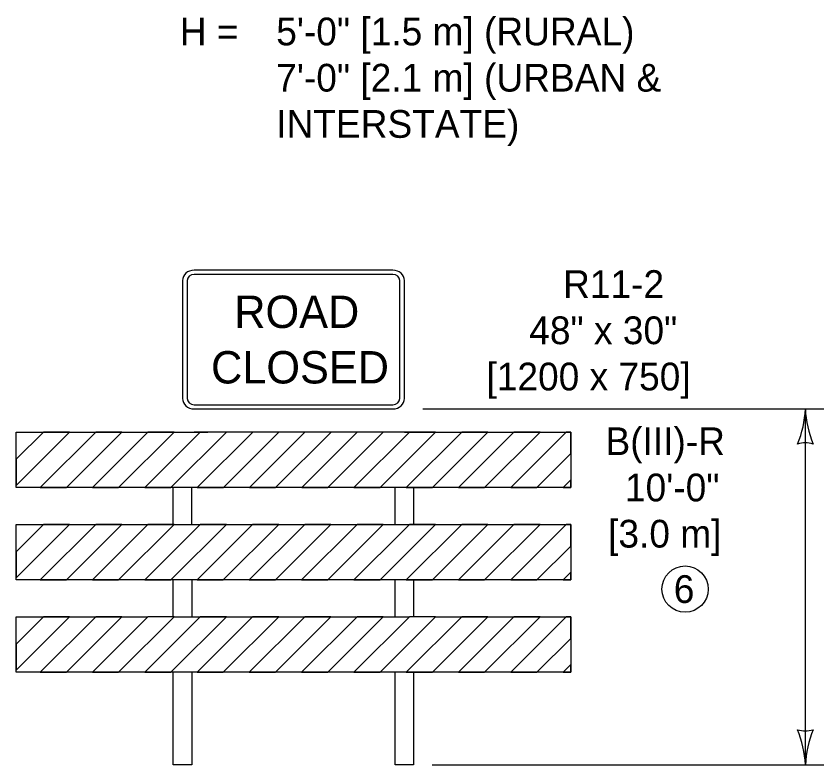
# Model space of a CAD drawing. Extents: x 49991.4 to 50021, y 49987.6 to 50011.4.
# Drawn here: x 50009.205 to 50010.952, y 49991.725 to 49993.345 of the extents above; entities that cross this region are included whole.
import ezdxf

# ---------------------------------------------------------------- set-up
doc = ezdxf.new("R2010")
doc.units = 0
for name, color, linetype in [('Level 1', 7, 'Continuous'), ('Level 2', 7, 'Continuous'), ('Level 3', 7, 'Continuous')]:
    doc.layers.add(name, color=color, linetype=linetype)

msp = doc.modelspace()

# ---------------------------------------------------------------- linework, layer by layer
at = {"layer": 'Level 1'}
for p, q in [((50010.0198, 49992.7954), (50009.5898, 49992.7954)), ((50010.0198, 49992.7864), (50009.5898, 49992.7864)), ((50009.5648, 49992.7729), (50009.5648, 49992.5179)), ((50009.5748, 49992.7729), (50009.5748, 49992.5179)), ((50010.0348, 49992.5179), (50010.0348, 49992.7729)), ((50010.0448, 49992.5179), (50010.0448, 49992.7729)), ((50009.5898, 49992.5044), (50010.0198, 49992.5044)), ((50009.5898, 49992.4954), (50010.0198, 49992.4954)), ((50009.2048, 49992.3299), (50009.3203, 49992.4454)), ((50009.2048, 49992.3865), (50009.2637, 49992.4454)), ((50009.2637, 49992.4454), (50009.2048, 49992.3865)), ((50009.2048, 49992.3299), (50009.3203, 49992.4454)), ((50009.2569, 49992.3254), (50009.3769, 49992.4454)), ((50009.3769, 49992.4454), (50009.2569, 49992.3254)), ((50009.3134, 49992.3254), (50009.4334, 49992.4454)), ((50009.3134, 49992.3254), (50009.4334, 49992.4454)), ((50009.37, 49992.3254), (50009.49, 49992.4454)), ((50009.49, 49992.4454), (50009.37, 49992.3254)), ((50009.4265, 49992.3254), (50009.5465, 49992.4454)), ((50009.4265, 49992.3254), (50009.5465, 49992.4454)), ((50009.4831, 49992.3254), (50009.6031, 49992.4454)), ((50009.5397, 49992.3254), (50009.6597, 49992.4454)), ((50009.5648, 49992.4454), (50009.6198, 49992.4454)), ((50010.0198, 49992.4454), (50009.5898, 49992.4454)), ((50009.5966, 49992.3254), (50009.7166, 49992.4454)), ((50009.6531, 49992.3254), (50009.7731, 49992.4454)), ((50009.7096, 49992.3254), (50009.8296, 49992.4454)), ((50009.7661, 49992.3254), (50009.8861, 49992.4454)), ((50009.8226, 49992.3254), (50009.9426, 49992.4454)), ((50009.8791, 49992.3254), (50009.9991, 49992.4454)), ((50009.9356, 49992.3254), (50010.0556, 49992.4454)), ((50010.0556, 49992.4454), (50009.9856, 49992.4454)), ((50009.9921, 49992.3254), (50010.1121, 49992.4454)), ((50010.0487, 49992.3254), (50010.1687, 49992.4454)), ((50010.1687, 49992.4454), (50010.0487, 49992.3254)), ((50010.1053, 49992.3254), (50010.2253, 49992.4454)), ((50010.1053, 49992.3254), (50010.2253, 49992.4454)), ((50010.1618, 49992.3254), (50010.2818, 49992.4454)), ((50010.2818, 49992.4454), (50010.1618, 49992.3254)), ((50010.2184, 49992.3254), (50010.3384, 49992.4454)), ((50010.2184, 49992.3254), (50010.3384, 49992.4454)), ((50010.275, 49992.3254), (50010.395, 49992.4454)), ((50010.395, 49992.4454), (50010.275, 49992.3254)), ((50010.3315, 49992.3254), (50010.4048, 49992.3987)), ((50010.3315, 49992.3254), (50010.4048, 49992.3987)), ((50010.3881, 49992.3254), (50010.4048, 49992.3421)), ((50010.4048, 49992.3421), (50010.3881, 49992.3254)), ((50009.5848, 49992.2455), (50009.5848, 49992.3254)), ((50010.0248, 49992.2455), (50010.0248, 49992.3254)), ((50009.2048, 49992.13), (50009.3203, 49992.2455)), ((50009.2048, 49992.1865), (50009.2637, 49992.2455)), ((50009.2637, 49992.2455), (50009.2048, 49992.1865)), ((50009.2048, 49992.13), (50009.3203, 49992.2455)), ((50009.2569, 49992.1255), (50009.3769, 49992.2455)), ((50009.3769, 49992.2455), (50009.2569, 49992.1255)), ((50009.3134, 49992.1255), (50009.4334, 49992.2455)), ((50009.3134, 49992.1255), (50009.4334, 49992.2455)), ((50009.37, 49992.1255), (50009.49, 49992.2455)), ((50009.49, 49992.2455), (50009.37, 49992.1255)), ((50009.4265, 49992.1255), (50009.5465, 49992.2455)), ((50009.4265, 49992.1255), (50009.5465, 49992.2455)), ((50009.4831, 49992.1255), (50009.6031, 49992.2455)), ((50009.5397, 49992.1255), (50009.6597, 49992.2455)), ((50009.5962, 49992.1255), (50009.7162, 49992.2455)), ((50009.6528, 49992.1255), (50009.7728, 49992.2455)), ((50009.7093, 49992.1255), (50009.8293, 49992.2455)), ((50009.7659, 49992.1255), (50009.8859, 49992.2455)), ((50009.8225, 49992.1255), (50009.9425, 49992.2455)), ((50009.879, 49992.1255), (50009.999, 49992.2455)), ((50010.0448, 49992.1782), (50010.1121, 49992.2455)), ((50010.0448, 49992.2347), (50010.0556, 49992.2455)), ((50010.0487, 49992.1255), (50010.1687, 49992.2455)), ((50010.1687, 49992.2455), (50010.0487, 49992.1255)), ((50010.1053, 49992.1255), (50010.2253, 49992.2455)), ((50010.1053, 49992.1255), (50010.2253, 49992.2455)), ((50010.1618, 49992.1255), (50010.2818, 49992.2455)), ((50010.2818, 49992.2455), (50010.1618, 49992.1255)), ((50010.2184, 49992.1255), (50010.3384, 49992.2455)), ((50010.2184, 49992.1255), (50010.3384, 49992.2455)), ((50010.275, 49992.1255), (50010.395, 49992.2455)), ((50010.395, 49992.2455), (50010.275, 49992.1255)), ((50009.9356, 49992.1255), (50010.0448, 49992.2347)), ((50010.3315, 49992.1255), (50010.4048, 49992.1987)), ((50010.3315, 49992.1255), (50010.4048, 49992.1987)), ((50009.9921, 49992.1255), (50010.0448, 49992.1782)), ((50010.3881, 49992.1255), (50010.4048, 49992.1422)), ((50010.4048, 49992.1422), (50010.3881, 49992.1255)), ((50009.2048, 49991.93), (50009.3203, 49992.0456)), ((50009.2048, 49991.9866), (50009.2637, 49992.0456)), ((50009.2637, 49992.0456), (50009.2048, 49991.9866)), ((50009.2048, 49991.93), (50009.3203, 49992.0456)), ((50009.2569, 49991.9256), (50009.3769, 49992.0456)), ((50009.3769, 49992.0456), (50009.2569, 49991.9256)), ((50009.3134, 49991.9256), (50009.4334, 49992.0456)), ((50009.3134, 49991.9256), (50009.4334, 49992.0456)), ((50009.37, 49991.9256), (50009.49, 49992.0456)), ((50009.49, 49992.0456), (50009.37, 49991.9256)), ((50009.4265, 49991.9256), (50009.5465, 49992.0456)), ((50009.4265, 49991.9256), (50009.5465, 49992.0456)), ((50009.4831, 49991.9256), (50009.6031, 49992.0456)), ((50009.6031, 49992.0456), (50009.4831, 49991.9256)), ((50009.5397, 49991.9256), (50009.6597, 49992.0456)), ((50009.5397, 49991.9256), (50009.6597, 49992.0456)), ((50009.5962, 49991.9256), (50009.7162, 49992.0456)), ((50009.7162, 49992.0456), (50009.5962, 49991.9256)), ((50009.6528, 49991.9256), (50009.7728, 49992.0456)), ((50009.6528, 49991.9256), (50009.7728, 49992.0456)), ((50009.7093, 49991.9256), (50009.8293, 49992.0456)), ((50009.8293, 49992.0456), (50009.7093, 49991.9256)), ((50009.7659, 49991.9256), (50009.8859, 49992.0456)), ((50009.7659, 49991.9256), (50009.8859, 49992.0456)), ((50009.8225, 49991.9256), (50009.9425, 49992.0456)), ((50009.9425, 49992.0456), (50009.8225, 49991.9256)), ((50009.879, 49991.9256), (50009.999, 49992.0456)), ((50009.879, 49991.9256), (50009.999, 49992.0456)), ((50009.9356, 49991.9256), (50010.0556, 49992.0456)), ((50010.0556, 49992.0456), (50009.9356, 49991.9256)), ((50009.9921, 49991.9256), (50010.1121, 49992.0456)), ((50009.9921, 49991.9256), (50010.1121, 49992.0456)), ((50010.0487, 49991.9256), (50010.1687, 49992.0456)), ((50010.1687, 49992.0456), (50010.0487, 49991.9256)), ((50010.1053, 49991.9256), (50010.2253, 49992.0456)), ((50010.1053, 49991.9256), (50010.2253, 49992.0456)), ((50010.1618, 49991.9256), (50010.2818, 49992.0456)), ((50010.2818, 49992.0456), (50010.1618, 49991.9256)), ((50010.2184, 49991.9256), (50010.3384, 49992.0456)), ((50010.2184, 49991.9256), (50010.3384, 49992.0456)), ((50010.275, 49991.9256), (50010.395, 49992.0456)), ((50010.395, 49992.0456), (50010.275, 49991.9256)), ((50010.3315, 49991.9256), (50010.4048, 49991.9988)), ((50010.3315, 49991.9256), (50010.4048, 49991.9988)), ((50010.3881, 49991.9256), (50010.4048, 49991.9423)), ((50010.4048, 49991.9423), (50010.3881, 49991.9256))]:
    msp.add_line(p, q, dxfattribs=at)
for points in [[(50010.0448, 49992.3254), (50009.2048, 49992.3254), (50009.2048, 49992.4454), (50009.5648, 49992.4454)], [(50009.3203, 49992.4454), (50009.2637, 49992.4454)], [(50009.4334, 49992.4454), (50009.3769, 49992.4454)], [(50009.6597, 49992.4454), (50009.6198, 49992.4454), (50009.6031, 49992.4454), (50009.4831, 49992.3254), (50009.5397, 49992.3254), (50009.6597, 49992.4454)], [(50009.5465, 49992.4454), (50009.49, 49992.4454)], [(50009.7731, 49992.4454), (50009.7166, 49992.4454), (50009.5966, 49992.3254), (50009.6531, 49992.3254), (50009.7731, 49992.4454)], [(50009.8861, 49992.4454), (50009.8296, 49992.4454), (50009.7096, 49992.3254), (50009.7661, 49992.3254), (50009.8861, 49992.4454)], [(50009.9991, 49992.4454), (50009.9856, 49992.4454), (50009.9426, 49992.4454), (50009.8226, 49992.3254), (50009.8791, 49992.3254), (50009.9991, 49992.4454)], [(50009.9356, 49992.3254), (50009.9921, 49992.3254), (50010.1121, 49992.4454), (50010.0556, 49992.4454), (50009.9356, 49992.3254)], [(50010.0448, 49992.4454), (50010.4048, 49992.4454), (50010.4048, 49992.3254), (50010.0448, 49992.3254)], [(50010.2253, 49992.4454), (50010.1687, 49992.4454)], [(50010.3384, 49992.4454), (50010.2818, 49992.4454)], [(50010.4048, 49992.3987), (50010.4048, 49992.4454), (50010.395, 49992.4454)], [(50009.2048, 49992.3865), (50009.2048, 49992.3299)], [(50010.3881, 49992.3254), (50010.4048, 49992.3254), (50010.4048, 49992.3421)], [(50009.2569, 49992.3254), (50009.3134, 49992.3254)], [(50009.37, 49992.3254), (50009.4265, 49992.3254)], [(50009.5448, 49992.2454), (50009.5448, 49992.3254)], [(50010.0487, 49992.3254), (50010.1053, 49992.3254)], [(50010.0648, 49992.3254), (50010.0648, 49992.2455)], [(50010.1618, 49992.3254), (50010.2184, 49992.3254)], [(50010.275, 49992.3254), (50010.3315, 49992.3254)], [(50010.0448, 49992.2455), (50010.4048, 49992.2455), (50010.4048, 49992.1255), (50009.2048, 49992.1255), (50009.2048, 49992.2455), (50010.0448, 49992.2455)], [(50009.3203, 49992.2455), (50009.2637, 49992.2455)], [(50009.4334, 49992.2455), (50009.3769, 49992.2455)], [(50009.6597, 49992.2455), (50009.6031, 49992.2455), (50009.4831, 49992.1255), (50009.5397, 49992.1255), (50009.6597, 49992.2455)], [(50009.5465, 49992.2455), (50009.49, 49992.2455)], [(50009.7728, 49992.2455), (50009.7162, 49992.2455), (50009.5962, 49992.1255), (50009.6528, 49992.1255), (50009.7728, 49992.2455)], [(50009.8859, 49992.2455), (50009.8293, 49992.2455), (50009.7093, 49992.1255), (50009.7659, 49992.1255), (50009.8859, 49992.2455)], [(50009.999, 49992.2455), (50009.9425, 49992.2455), (50009.8225, 49992.1255), (50009.879, 49992.1255), (50009.999, 49992.2455)], [(50009.9356, 49992.1255), (50009.9921, 49992.1255), (50010.0448, 49992.1782), (50010.1121, 49992.2455), (50010.0648, 49992.2455), (50010.0556, 49992.2455), (50010.0448, 49992.2347), (50009.9356, 49992.1255)], [(50010.2253, 49992.2455), (50010.1687, 49992.2455)], [(50010.3384, 49992.2455), (50010.2818, 49992.2455)], [(50010.4048, 49992.1987), (50010.4048, 49992.2455), (50010.395, 49992.2455)], [(50009.2048, 49992.1865), (50009.2048, 49992.13)], [(50010.3881, 49992.1255), (50010.4048, 49992.1255), (50010.4048, 49992.1422)], [(50009.2569, 49992.1255), (50009.3134, 49992.1255)], [(50009.37, 49992.1255), (50009.4265, 49992.1255)], [(50009.5448, 49992.0456), (50009.5448, 49992.1255)], [(50009.5848, 49992.1255), (50009.5848, 49992.0456)], [(50010.0248, 49992.0456), (50010.0248, 49992.1255)], [(50010.0487, 49992.1255), (50010.1053, 49992.1255)], [(50010.0648, 49992.1255), (50010.0648, 49992.0456)], [(50010.1618, 49992.1255), (50010.2184, 49992.1255)], [(50010.275, 49992.1255), (50010.3315, 49992.1255)], [(50010.1121, 49992.0456), (50010.4048, 49992.0456), (50010.4048, 49991.9256), (50009.2048, 49991.9256), (50009.2048, 49992.0456), (50009.49, 49992.0456)], [(50009.3203, 49992.0456), (50009.2637, 49992.0456)], [(50009.4334, 49992.0456), (50009.3769, 49992.0456)], [(50009.5465, 49992.0456), (50009.49, 49992.0456)], [(50009.5465, 49992.0456), (50010.0556, 49992.0456)], [(50009.6597, 49992.0456), (50009.6031, 49992.0456)], [(50009.7728, 49992.0456), (50009.7162, 49992.0456)], [(50009.8859, 49992.0456), (50009.8293, 49992.0456)], [(50009.999, 49992.0456), (50009.9425, 49992.0456)], [(50010.1121, 49992.0456), (50010.0556, 49992.0456)], [(50010.2253, 49992.0456), (50010.1687, 49992.0456)], [(50010.3384, 49992.0456), (50010.2818, 49992.0456)], [(50010.4048, 49991.9988), (50010.4048, 49992.0456), (50010.395, 49992.0456)], [(50009.2048, 49991.9866), (50009.2048, 49991.93)], [(50010.3881, 49991.9256), (50010.4048, 49991.9256), (50010.4048, 49991.9423)], [(50009.2569, 49991.9256), (50009.3134, 49991.9256)], [(50009.37, 49991.9256), (50009.4265, 49991.9256)], [(50009.4831, 49991.9256), (50009.5397, 49991.9256)], [(50009.5848, 49991.9254), (50009.5848, 49991.7254), (50009.5448, 49991.7254), (50009.5448, 49991.9254)], [(50009.5962, 49991.9256), (50009.6528, 49991.9256)], [(50009.7093, 49991.9256), (50009.7659, 49991.9256)], [(50009.8225, 49991.9256), (50009.879, 49991.9256)], [(50009.9356, 49991.9256), (50009.9921, 49991.9256)], [(50010.0648, 49991.9254), (50010.0648, 49991.7254), (50010.0248, 49991.7254), (50010.0248, 49991.9254)], [(50010.0487, 49991.9256), (50010.1053, 49991.9256)], [(50010.1618, 49991.9256), (50010.2184, 49991.9256)], [(50010.275, 49991.9256), (50010.3315, 49991.9256)]]:
    msp.add_lwpolyline(points, dxfattribs=at)
for centre, major_axis, start_param, end_param in [((50009.5898, 49992.7729), (-0.025, 0), 4.712389, 6.283185), ((50010.0198, 49992.7729), (0.025, 0), 0, 1.570796), ((50009.5898, 49992.7729), (-0.015, 0), 4.712389, 6.283185), ((50010.0198, 49992.7729), (0.015, 0), 0, 1.570796), ((50009.5898, 49992.5179), (-0.025, 0), 0, 1.570796), ((50009.5898, 49992.5179), (-0.015, 0), 0, 1.570796), ((50010.0198, 49992.5179), (0.025, 0), 4.712389, 6.283185), ((50010.0198, 49992.5179), (0.015, 0), 4.712389, 6.283185)]:
    msp.add_ellipse(centre, major_axis=major_axis, ratio=0.9, start_param=start_param, end_param=end_param, dxfattribs=at)
at = {"layer": 'Level 2'}
msp.add_circle((50010.652, 49992.1056), 0.05, dxfattribs=at)
at = {"layer": 'Level 3'}
for p, q in [((50010.0848, 49992.4954), (50010.9522, 49992.4954)), ((50010.9122, 49991.7254), (50010.9122, 49992.4954)), ((50010.1048, 49991.7254), (50010.9522, 49991.7254))]:
    msp.add_line(p, q, dxfattribs=at)
for centre, radius, start, end in [((50010.6901, 49992.5046), 0.2223, 337.456, 357.6395), ((50011.1449, 49992.5069), 0.233, 182.8273, 202.0772), ((50010.9122, 49992.3672), 0.0548, 72.1388, 107.8612), ((50010.9122, 49991.8536), 0.0548, 252.1388, 287.8612), ((50010.6795, 49991.7139), 0.233, 2.8273, 22.0772), ((50011.1344, 49991.7162), 0.2223, 157.456, 177.6395)]:
    msp.add_arc(centre, radius, start, end, dxfattribs=at)

# ---------------------------------------------------------------- texts
at = {"layer": 'Level 1'}
for s, p in [('ROAD', (50009.6767, 49992.6704)), ('CLOSED', (50009.6265, 49992.5504))]:
    msp.add_text(s, height=0.07, dxfattribs=at).set_placement(p)
at = {"layer": 'Level 2'}
for s, p in [('H =', (50009.559, 49993.2818)), ('5\'-0" [1.5 m] (RURAL)', (50009.7675, 49993.2818)), ('7\'-0" [2.1 m] (URBAN &', (50009.7675, 49993.1818)), ('INTERSTATE)', (50009.7675, 49993.0818)), ('R11-2', (50010.3881, 49992.7354)), ('48" x 30"', (50010.3149, 49992.6354)), ('[1200 x 750]', (50010.2224, 49992.5354)), ('B(III)-R', (50010.4798, 49992.3954)), (' 10\'-0"', (50010.4997, 49992.2954)), ('[3.0 m]', (50010.4855, 49992.1954)), ('6', (50010.6275, 49992.0756))]:
    msp.add_text(s, height=0.06, dxfattribs=at).set_placement(p)

doc.saveas('drawing.dxf')
